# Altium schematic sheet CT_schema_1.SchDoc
size 404 x 338 mm
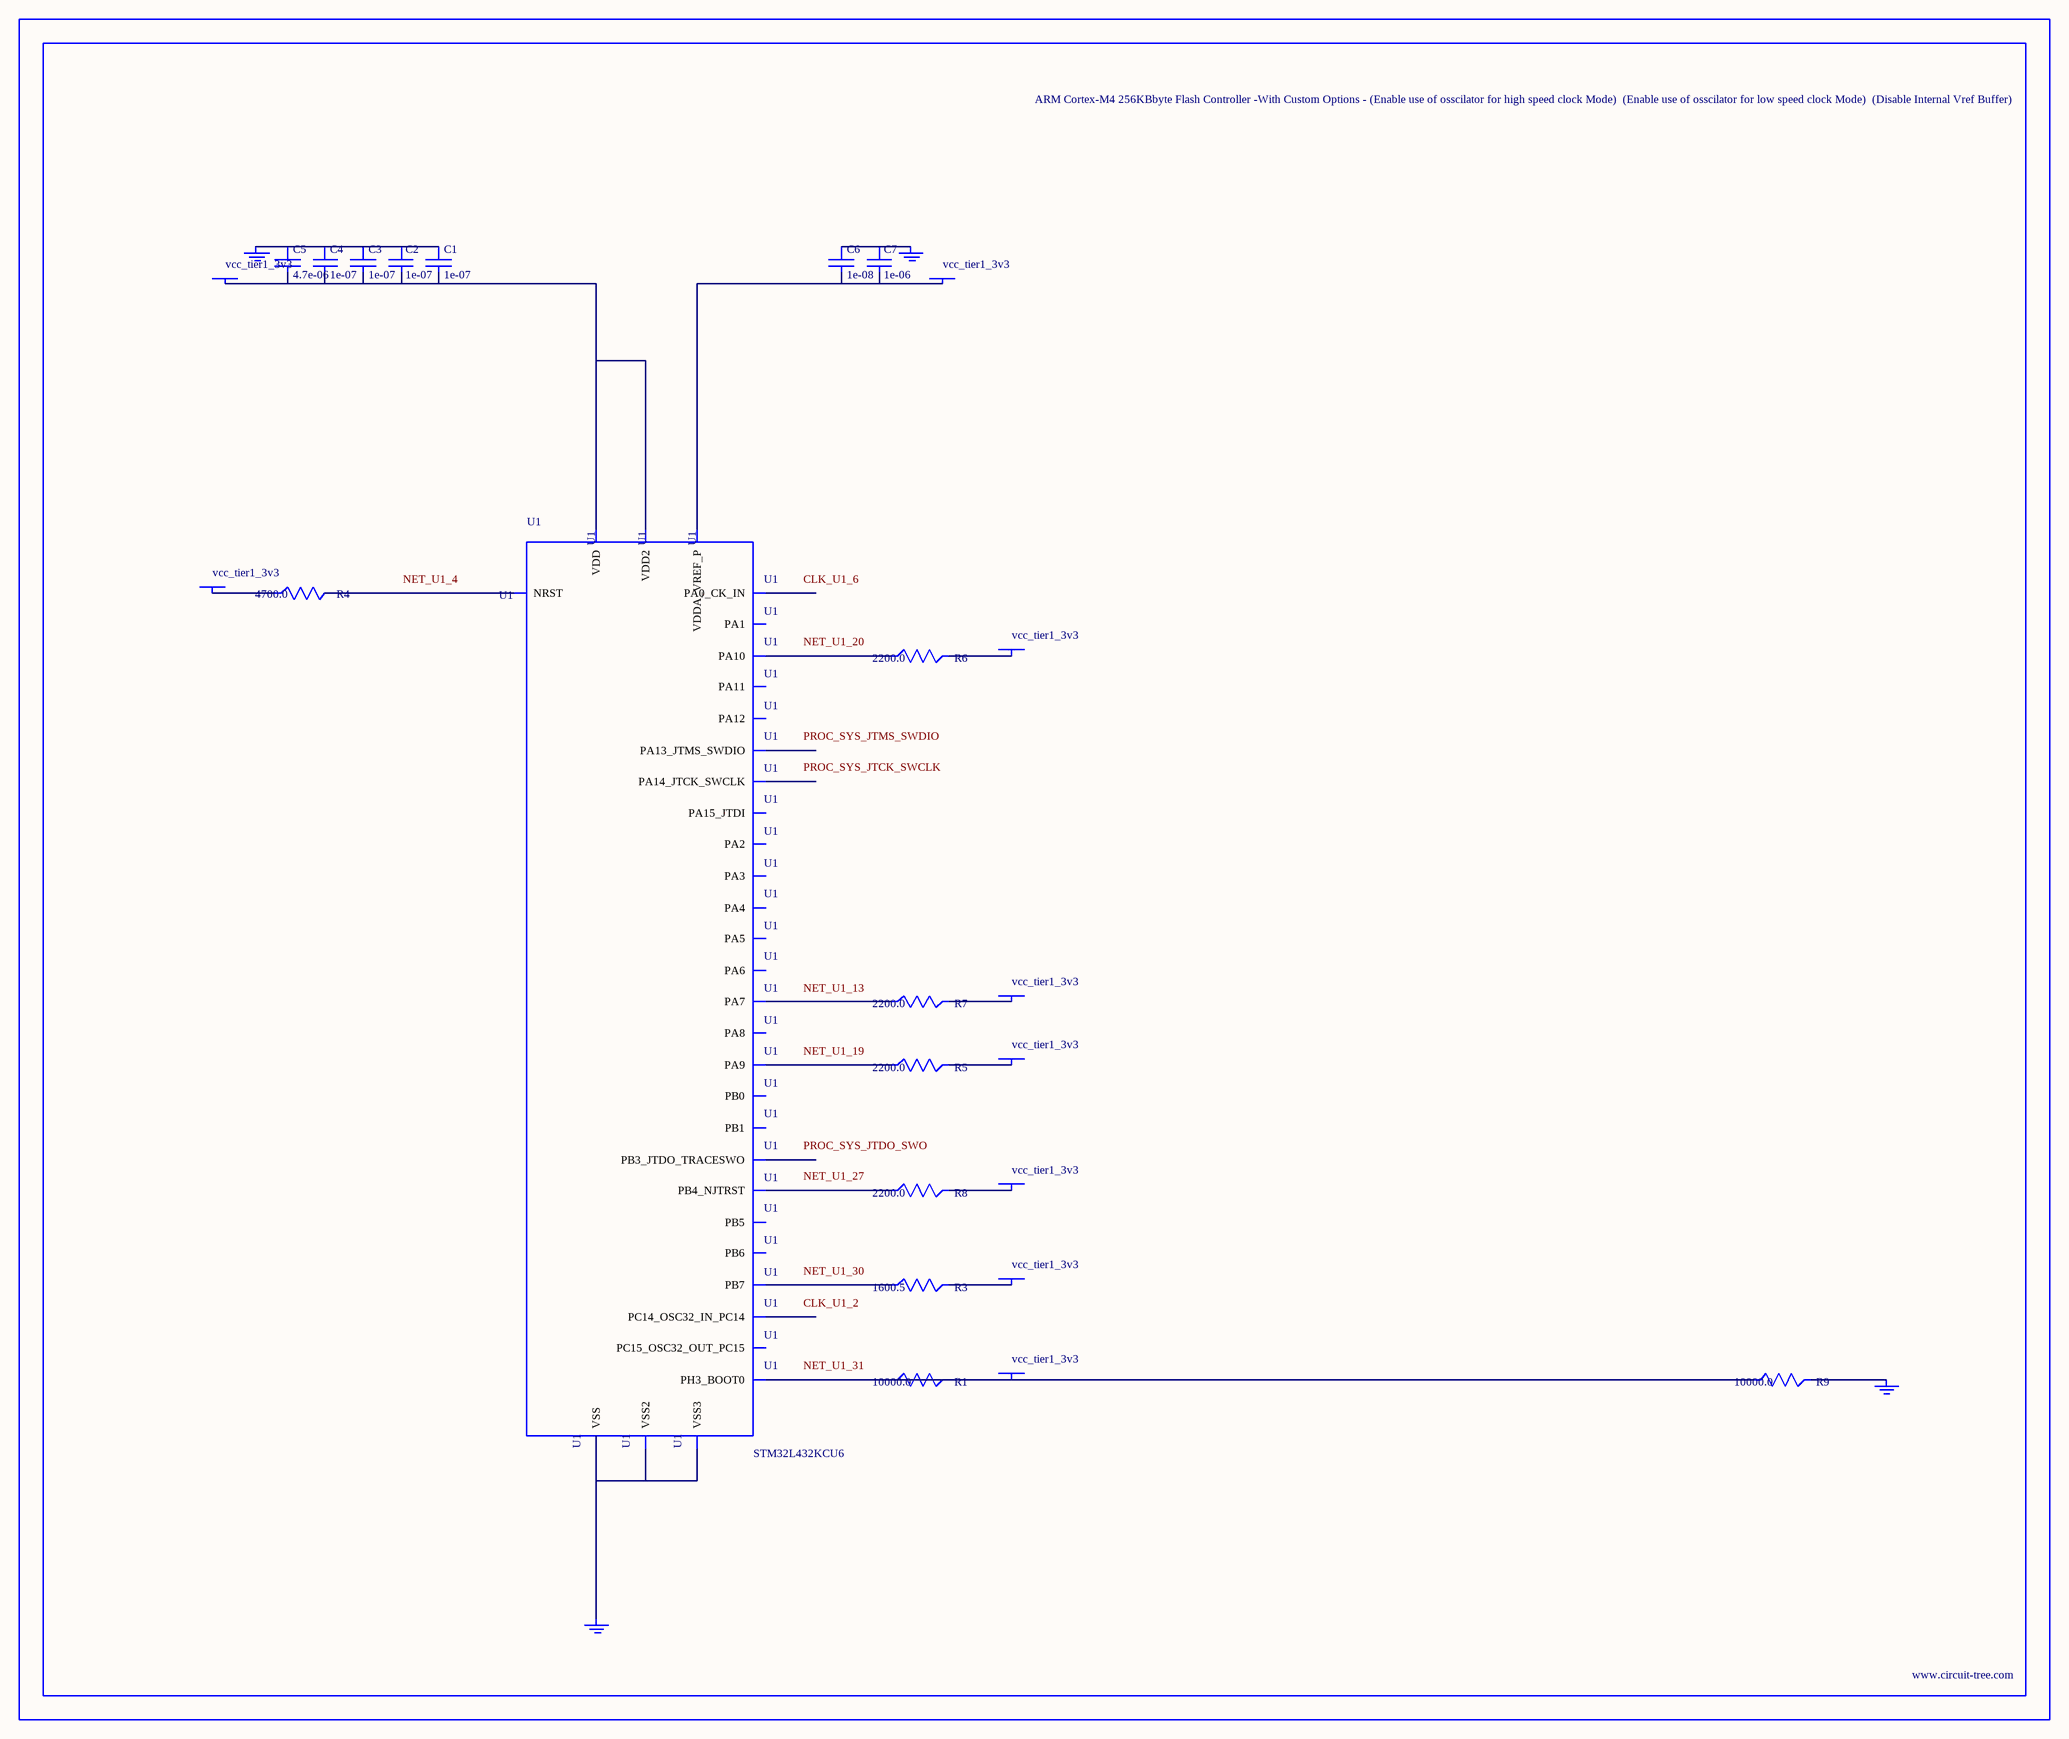
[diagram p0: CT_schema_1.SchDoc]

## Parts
BORDER0  (no value)
C1  1e-07  [C0603]
C2  1e-07  [C0603]
C3  1e-07  [C0603]
C4  1e-07  [C0603]
C5  4.7e-06  [C0603]
C6  1e-08  [C0603]
C7  1e-06  [C0603]
GND_INSTANCE_0_0  (no value)
GND_INSTANCE_0_1  (no value)
GND_INSTANCE_0_2  (no value)
GND_INSTANCE_0_3  (no value)
POWER_INSTANCE_0_0  vcc_tier1_3v3
POWER_INSTANCE_0_1  vcc_tier1_3v3
POWER_INSTANCE_0_2  vcc_tier1_3v3
POWER_INSTANCE_0_3  vcc_tier1_3v3
POWER_INSTANCE_0_4  vcc_tier1_3v3
POWER_INSTANCE_0_5  vcc_tier1_3v3
POWER_INSTANCE_0_6  vcc_tier1_3v3
POWER_INSTANCE_0_7  vcc_tier1_3v3
POWER_INSTANCE_0_8  vcc_tier1_3v3
R1  10000.0  [R0603]
R3  1600.5  [R0603]
R4  4700.0  [R0603]
R5  2200.0  [R0603]
R6  2200.0  [R0603]
R7  2200.0  [R0603]
R8  2200.0  [R0603]
R9  10000.0  [R0603]
U1  STM32L432KCU6  [UFQFPN32]

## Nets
NetC1_1: C1.1 C2.1 C3.1 C4.1 C5.1 GND_INSTANCE_0_0.0(GND)
NetC1_2: C1.2 C2.2 C3.2 C4.2 C5.2 POWER_INSTANCE_0_0.0(PWR) U1.1(VDD) U1.17(VDD2)
NetC6_1: C6.1 C7.1 GND_INSTANCE_0_1.0(GND)
NetC6_2: C6.2 C7.2 POWER_INSTANCE_0_1.0(PWR) U1.5(VDDA_VREF_P)
NetGND_INSTANCE_0_2_0: GND_INSTANCE_0_2.0(GND) R9.2
NetGND_INSTANCE_0_3_0: GND_INSTANCE_0_3.0(GND) U1.16(VSS) U1.32(VSS2) U1.EPAD(VSS3)
NetPOWER_INSTANCE_0_2_0: POWER_INSTANCE_0_2.0(PWR) R4.1
NetPOWER_INSTANCE_0_3_0: POWER_INSTANCE_0_3.0(PWR) R7.2
NetPOWER_INSTANCE_0_4_0: POWER_INSTANCE_0_4.0(PWR) R5.2
NetPOWER_INSTANCE_0_5_0: POWER_INSTANCE_0_5.0(PWR) R6.2
NetPOWER_INSTANCE_0_6_0: POWER_INSTANCE_0_6.0(PWR) R8.2
NetPOWER_INSTANCE_0_7_0: POWER_INSTANCE_0_7.0(PWR) R3.2
NetPOWER_INSTANCE_0_8_0: POWER_INSTANCE_0_8.0(PWR) R1.1 R1.2 R9.1 U1.31(PH3_BOOT0)
NetR3_1: R3.1 U1.30(PB7)
NetR4_2: R4.2 U1.4(NRST)
NetR5_1: R5.1 U1.19(PA9)
NetR6_1: R6.1 U1.20(PA10)
NetR7_1: R7.1 U1.13(PA7)
NetR8_1: R8.1 U1.27(PB4_NJTRST)

Not connected (* = marked no-connect by the designer): U1 2(PC14_OSC32_IN_PC14) 3(PC15_OSC32_OUT_PC15) 6(PA0_CK_IN) 7(PA1) 8(PA2) 9(PA3) 10(PA4) 11(PA5) 12(PA6) 14(PB0) 15(PB1) 18(PA8) 21(PA11) 22(PA12) 23(PA13_JTMS_SWDIO) 24(PA14_JTCK_SWCLK) 25(PA15_JTDI) 26(PB3_JTDO_TRACESWO) 28(PB5) 29(PB6)

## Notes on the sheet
- Labels drawn without touching a wire or pin: CLK_U1_2, CLK_U1_6, NET_U1_4, NET_U1_13, NET_U1_19, NET_U1_20, NET_U1_27, NET_U1_30, NET_U1_31, PROC_SYS_JTCK_SWCLK, PROC_SYS_JTDO_SWO, PROC_SYS_JTMS_SWDIO

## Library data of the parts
BORDER0 = BORDER_PAGE0
C1-C4 = 06035C104K4Z2A
C5 = GRM188R6YA475KE15D
C6 = 06035C103K4Z2A
C7 = C0603C105K3RACTU
GND_INSTANCE_0_0-GND_INSTANCE_0_3 = GND
POWER_INSTANCE_0_0-POWER_INSTANCE_0_8 = PWR
R1 R9 = RC0603JR-0710KL
R3 = R3
R4 = RC0603JR-074K7L
R5-R8 = RC0603JR-072K2L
